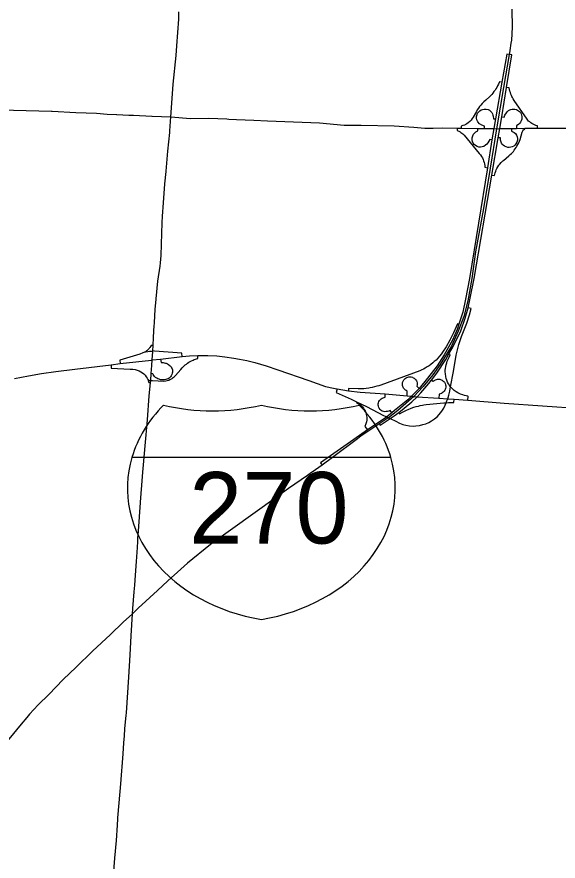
# Model space of a CAD drawing. Extents: x 0 to 34, y 0 to 22.
# Drawn here: x 7.083 to 7.784, y 16.072 to 17.165 of the extents above; entities that cross this region are included whole.
import ezdxf

# ---------------------------------------------------------------- set-up
doc = ezdxf.new("R2010")
doc.units = 0
for name, color, linetype in [('GM_X_Interchange_Ramps', 7, 'Continuous'), ('GM_X_Interstate_Route', 7, 'Continuous'), ('GM_X_Interstate_Shield', 7, 'Continuous'), ('GM_X_State_Route', 7, 'Continuous'), ('GM_X_US_Route', 7, 'Continuous')]:
    doc.layers.add(name, color=color, linetype=linetype)

msp = doc.modelspace()

# ---------------------------------------------------------------- linework, layer by layer
at = {"layer": 'GM_X_Interchange_Ramps'}
for points in [[(7.7204, 17.1167), (7.7175, 17.1172), (7.7111, 17.0809), (7.7027, 17.0331), (7.7005, 17.0206), (7.6981, 17.006), (7.6923, 16.97), (7.669, 16.8266), (7.664, 16.7998), (7.6603, 16.7829), (7.6552, 16.7672), (7.6529, 16.7605), (7.647, 16.7467), (7.6362, 16.7275), (7.627, 16.7132), (7.6148, 16.6972), (7.6039, 16.6842), (7.6023, 16.6823), (7.594, 16.674), (7.5893, 16.6692), (7.5721, 16.6553), (7.5683, 16.6523), (7.5618, 16.6472), (7.5616, 16.647), (7.537, 16.6303), (7.519, 16.6181), (7.4761, 16.5876), (7.4782, 16.5848)], [(7.5522, 16.6381), (7.5535, 16.6363), (7.5662, 16.645), (7.5715, 16.6487), (7.5774, 16.6528), (7.5845, 16.6584), (7.5943, 16.6669), (7.6011, 16.6734), (7.606, 16.6782), (7.6164, 16.6904), (7.6199, 16.6949), (7.6268, 16.7037), (7.6384, 16.7216), (7.6424, 16.7287), (7.646, 16.7352), (7.6515, 16.7451), (7.6577, 16.7587), (7.6636, 16.7752), (7.6675, 16.7885), (7.6701, 16.801), (7.6751, 16.8266), (7.698, 16.9605), (7.7063, 17.0089), (7.7083, 17.0206), (7.7083, 17.0207), (7.7108, 17.0361), (7.717, 17.0738), (7.7239, 17.1162), (7.7204, 17.1167)], [(7.7111, 17.0809), (7.7078, 17.0814), (7.7065, 17.0783), (7.7055, 17.0761), (7.7044, 17.0741), (7.7034, 17.0723), (7.7022, 17.0704), (7.7008, 17.0685), (7.6994, 17.0666), (7.6979, 17.0648), (7.697, 17.0638), (7.6956, 17.0624), (7.6902, 17.0574), (7.6877, 17.0552), (7.6856, 17.0532), (7.6837, 17.0511), (7.6822, 17.0492), (7.6807, 17.0471), (7.6792, 17.045), (7.678, 17.0429), (7.6739, 17.0356), (7.6726, 17.0336), (7.6712, 17.0317), (7.6695, 17.0299), (7.6674, 17.0282), (7.6657, 17.027), (7.6642, 17.0261), (7.6625, 17.0252), (7.6606, 17.0245), (7.6582, 17.0238), (7.6582, 17.0213)], [(7.7571, 17.0213), (7.757, 17.0242), (7.7551, 17.0248), (7.7533, 17.0255), (7.7516, 17.0263), (7.75, 17.0271), (7.7485, 17.0281), (7.7471, 17.0292), (7.7457, 17.0304), (7.7446, 17.0316), (7.7437, 17.0327), (7.7271, 17.0571), (7.7258, 17.059), (7.7247, 17.0608), (7.724, 17.0622), (7.7233, 17.0637), (7.7226, 17.0654), (7.722, 17.0672), (7.7214, 17.0692), (7.7206, 17.0733), (7.717, 17.0738)], [(7.6884, 17.0208), (7.6885, 17.0237), (7.6851, 17.025), (7.6822, 17.0267), (7.6797, 17.0294), (7.6786, 17.032), (7.6782, 17.0343), (7.6782, 17.0365), (7.6788, 17.0389), (7.6796, 17.0405), (7.681, 17.0424), (7.6824, 17.0437), (7.6842, 17.0449), (7.686, 17.0456), (7.6882, 17.046), (7.6905, 17.0459), (7.6931, 17.0452), (7.6948, 17.0444), (7.6965, 17.043), (7.6979, 17.0414), (7.6989, 17.0398), (7.6995, 17.0381), (7.6998, 17.0366), (7.7001, 17.0335), (7.7027, 17.0331)], [(7.7108, 17.0361), (7.7141, 17.0356), (7.715, 17.0379), (7.7168, 17.0412), (7.7179, 17.0425), (7.7197, 17.0441), (7.7212, 17.045), (7.7228, 17.0456), (7.7242, 17.0459), (7.7257, 17.046), (7.7278, 17.0459), (7.7299, 17.0453), (7.7313, 17.0446), (7.7326, 17.0438), (7.7339, 17.0427), (7.735, 17.0413), (7.7358, 17.0399), (7.7365, 17.0382), (7.7369, 17.0365), (7.737, 17.0349), (7.7368, 17.033), (7.7362, 17.0309), (7.7353, 17.0291), (7.734, 17.0274), (7.7329, 17.0264), (7.7298, 17.0242), (7.7299, 17.0209)], [(7.6531, 17.0214), (7.653, 17.0184), (7.6554, 17.0173), (7.6569, 17.0165), (7.658, 17.0157), (7.6593, 17.0148), (7.6606, 17.0137), (7.662, 17.0122), (7.6817, 16.9886), (7.6833, 16.9865), (7.6845, 16.9847), (7.6857, 16.9827), (7.6866, 16.9808), (7.6873, 16.9789), (7.688, 16.9769), (7.6885, 16.9749), (7.6889, 16.973), (7.6891, 16.9705), (7.6923, 16.97)], [(7.6981, 17.006), (7.6953, 17.0064), (7.6928, 17.0021), (7.6914, 17.0005), (7.6899, 16.999), (7.6878, 16.9976), (7.6856, 16.9969), (7.6833, 16.9966), (7.6811, 16.9968), (7.6788, 16.9975), (7.6769, 16.9986), (7.6752, 17.0001), (7.674, 17.0018), (7.673, 17.0039), (7.6725, 17.0061), (7.6726, 17.0089), (7.6732, 17.0112), (7.6743, 17.0133), (7.6758, 17.0151), (7.6774, 17.0164), (7.6799, 17.0177), (7.68, 17.0209)], [(7.698, 16.9605), (7.7014, 16.96), (7.7024, 16.9635), (7.703, 16.9653), (7.7037, 16.9671), (7.7046, 16.969), (7.7058, 16.9711), (7.7071, 16.9731), (7.7083, 16.9747), (7.7101, 16.9767), (7.7121, 16.9787), (7.7131, 16.9795), (7.7201, 16.9855), (7.7218, 16.9869), (7.7233, 16.9883), (7.7246, 16.9897), (7.7259, 16.991), (7.7271, 16.9925), (7.7284, 16.9943), (7.7295, 16.996), (7.7306, 16.9978), (7.7329, 17.0024), (7.7346, 17.0065), (7.7375, 17.016), (7.7381, 17.0177), (7.7391, 17.019), (7.7406, 17.02), (7.7406, 17.021)], [(7.7234, 17.0208), (7.7235, 17.0175), (7.727, 17.0157), (7.7286, 17.0141), (7.73, 17.0121), (7.7308, 17.0098), (7.7311, 17.0077), (7.7311, 17.0056), (7.7304, 17.003), (7.7293, 17.001), (7.7278, 16.9992), (7.7264, 16.9981), (7.7244, 16.997), (7.7226, 16.9964), (7.7206, 16.9962), (7.7186, 16.9963), (7.7164, 16.9969), (7.7143, 16.9979), (7.7127, 16.9992), (7.7116, 17.0004), (7.7107, 17.0019), (7.7101, 17.0032), (7.7094, 17.0056), (7.7091, 17.0085), (7.7063, 17.0089)], [(7.4975, 16.6834), (7.4965, 16.6787), (7.5156, 16.67), (7.5226, 16.6667), (7.5358, 16.6605), (7.5576, 16.6492), (7.5618, 16.6472), (7.5641, 16.6461), (7.5662, 16.645), (7.5735, 16.6415), (7.5783, 16.6391), (7.5825, 16.6375), (7.5867, 16.6364), (7.5914, 16.6356), (7.596, 16.6354), (7.5997, 16.6355), (7.6045, 16.6361), (7.6088, 16.6372), (7.6126, 16.6384), (7.6163, 16.6401), (7.62, 16.6421), (7.6236, 16.6446), (7.627, 16.6474), (7.6299, 16.6504), (7.6333, 16.6546), (7.6358, 16.6587), (7.6376, 16.6622), (7.639, 16.6656), (7.6399, 16.6678), (7.6409, 16.6706), (7.641, 16.6708), (7.6423, 16.6753), (7.6434, 16.6805), (7.6446, 16.6863), (7.6484, 16.706), (7.6519, 16.7272), (7.6535, 16.7341), (7.6551, 16.7409), (7.6587, 16.7514), (7.6654, 16.7686), (7.669, 16.7795), (7.6712, 16.7875), (7.6675, 16.7885)], [(7.6552, 16.7672), (7.6537, 16.7678), (7.6484, 16.7563), (7.6436, 16.7468), (7.6387, 16.7379), (7.6341, 16.731), (7.6326, 16.7288), (7.6303, 16.7259), (7.6281, 16.7233), (7.6258, 16.7209), (7.6235, 16.7188), (7.6215, 16.7171), (7.6188, 16.715), (7.6168, 16.7135), (7.6144, 16.712), (7.6116, 16.7103), (7.6095, 16.7092), (7.6071, 16.7081), (7.6047, 16.707), (7.5544, 16.6884), (7.5515, 16.6875), (7.549, 16.6868), (7.5458, 16.686), (7.5429, 16.6854), (7.5405, 16.685), (7.5386, 16.6846), (7.5351, 16.6841), (7.5322, 16.6837), (7.525, 16.6835), (7.5125, 16.6841), (7.5121, 16.681)], [(7.2592, 16.7397), (7.2568, 16.7398), (7.2558, 16.7382), (7.2552, 16.7373), (7.2546, 16.7366), (7.2539, 16.7357), (7.2531, 16.7349), (7.2524, 16.7342), (7.2514, 16.7333), (7.2506, 16.7326), (7.2493, 16.7317), (7.2459, 16.7301), (7.2421, 16.7286), (7.2159, 16.7206), (7.2164, 16.7163)], [(7.2587, 16.7317), (7.2572, 16.7319), (7.2562, 16.7319), (7.2545, 16.7318), (7.2523, 16.7314), (7.2498, 16.7309), (7.2493, 16.7317)], [(7.2967, 16.7256), (7.2963, 16.7297), (7.2608, 16.7324), (7.2588, 16.7326)], [(7.256, 16.6945), (7.2584, 16.6943), (7.2731, 16.6937), (7.2758, 16.694), (7.2775, 16.6944), (7.2795, 16.695), (7.2808, 16.6955), (7.2822, 16.6961), (7.2838, 16.6971), (7.2852, 16.6981), (7.2866, 16.6992), (7.2882, 16.7008), (7.2951, 16.7086), (7.2966, 16.7106), (7.2977, 16.7118), (7.2993, 16.7134), (7.3007, 16.7145), (7.3022, 16.7157), (7.3039, 16.717), (7.3054, 16.718), (7.3072, 16.719), (7.309, 16.7199), (7.3109, 16.7207), (7.3125, 16.7214), (7.317, 16.7227), (7.3171, 16.7268)], [(7.2689, 16.7222), (7.2694, 16.7178), (7.2721, 16.7175), (7.2736, 16.7172), (7.2751, 16.7169), (7.2762, 16.7166), (7.2776, 16.716), (7.279, 16.7152), (7.2801, 16.7144), (7.2814, 16.7132), (7.2824, 16.7121), (7.2831, 16.7108), (7.2837, 16.7095), (7.2841, 16.7081), (7.2842, 16.7067), (7.2842, 16.705), (7.2839, 16.7037), (7.2835, 16.7022), (7.2827, 16.7006), (7.2817, 16.6992), (7.281, 16.6983), (7.2798, 16.6973), (7.2787, 16.6967), (7.277, 16.696), (7.2755, 16.6956), (7.274, 16.6953), (7.2722, 16.6951), (7.2705, 16.6952), (7.2688, 16.6954), (7.267, 16.6959), (7.2654, 16.6965), (7.2638, 16.6973), (7.2623, 16.6984), (7.261, 16.6997), (7.2601, 16.7009), (7.2593, 16.7022), (7.2589, 16.7032), (7.2568, 16.7033)], [(7.6669, 16.669), (7.6673, 16.6738), (7.667, 16.6739), (7.6647, 16.6744), (7.6628, 16.6749), (7.6603, 16.6756), (7.6574, 16.6766), (7.654, 16.6783), (7.6516, 16.6797), (7.6492, 16.6815), (7.647, 16.6835), (7.6456, 16.685), (7.6446, 16.6863), (7.6432, 16.6881), (7.6419, 16.6901), (7.6407, 16.6924), (7.6396, 16.6949), (7.6389, 16.6971), (7.6383, 16.6995), (7.6378, 16.7028), (7.6376, 16.7054), (7.6376, 16.7077), (7.6378, 16.7099), (7.6383, 16.7127), (7.6388, 16.7148), (7.6395, 16.7171), (7.6403, 16.7192), (7.6414, 16.722), (7.6427, 16.7247), (7.6442, 16.7277), (7.6424, 16.7287)], [(7.2046, 16.7148), (7.2049, 16.7104), (7.2296, 16.7091), (7.2329, 16.7089), (7.2359, 16.7084), (7.2386, 16.7077), (7.2409, 16.7068), (7.2432, 16.7057), (7.2454, 16.7042), (7.2471, 16.7028), (7.2487, 16.7013), (7.2502, 16.6993), (7.2514, 16.6973), (7.2524, 16.6956), (7.2526, 16.695), (7.2528, 16.6938), (7.253, 16.6929), (7.2534, 16.6916), (7.2558, 16.6914)], [(7.5881, 16.6745), (7.5885, 16.6804), (7.5881, 16.6806), (7.587, 16.6812), (7.5862, 16.6818), (7.5852, 16.6826), (7.5844, 16.6835), (7.5836, 16.6845), (7.583, 16.6856), (7.5827, 16.6865), (7.5823, 16.6877), (7.5822, 16.6888), (7.5822, 16.6904), (7.5824, 16.6916), (7.5827, 16.6928), (7.5834, 16.6943), (7.5841, 16.6954), (7.5848, 16.6962), (7.5857, 16.697), (7.5868, 16.6977), (7.5879, 16.6983), (7.5892, 16.6988), (7.5903, 16.699), (7.5918, 16.6991), (7.5935, 16.6989), (7.595, 16.6985), (7.5962, 16.698), (7.5975, 16.6972), (7.5986, 16.6962), (7.5995, 16.6951), (7.6002, 16.694), (7.6007, 16.6929), (7.6011, 16.6915), (7.6013, 16.6901), (7.6012, 16.6888), (7.601, 16.6872), (7.6039, 16.6842)], [(7.2524, 16.6956), (7.2528, 16.6957), (7.2536, 16.6949), (7.2545, 16.6944), (7.256, 16.6945)], [(7.6199, 16.6949), (7.6219, 16.6935), (7.6232, 16.6944), (7.6249, 16.6953), (7.6262, 16.6958), (7.6276, 16.696), (7.629, 16.6961), (7.6305, 16.6959), (7.6323, 16.6953), (7.6335, 16.6948), (7.6347, 16.6939), (7.6358, 16.6929), (7.6365, 16.692), (7.6374, 16.6905), (7.6379, 16.6889), (7.6382, 16.6873), (7.6382, 16.6859), (7.638, 16.6842), (7.6376, 16.6829), (7.6371, 16.6818), (7.6361, 16.6804), (7.6351, 16.6793), (7.6338, 16.6783), (7.6326, 16.6777), (7.6296, 16.6766), (7.6292, 16.6714)], [(7.5226, 16.6667), (7.5222, 16.666), (7.5241, 16.6651), (7.5262, 16.6638), (7.5283, 16.6622), (7.5303, 16.6602), (7.5317, 16.6584), (7.5328, 16.6567), (7.5337, 16.6551), (7.5346, 16.653), (7.5353, 16.6508), (7.5357, 16.6487), (7.5359, 16.6467), (7.536, 16.6451), (7.5359, 16.6429), (7.5356, 16.6409), (7.5349, 16.6384), (7.5336, 16.6348), (7.537, 16.6303)], [(7.5683, 16.6523), (7.5661, 16.6553), (7.5646, 16.6548), (7.5628, 16.6543), (7.5611, 16.654), (7.5594, 16.6539), (7.5575, 16.6542), (7.5559, 16.6548), (7.5546, 16.6557), (7.5532, 16.6569), (7.5522, 16.6583), (7.5516, 16.6594), (7.551, 16.6612), (7.5508, 16.6626), (7.5509, 16.6643), (7.5512, 16.6656), (7.5518, 16.6671), (7.5525, 16.6683), (7.5535, 16.6695), (7.5548, 16.6706), (7.5561, 16.6714), (7.5596, 16.6727), (7.5598, 16.6769)], [(7.5774, 16.6528), (7.5785, 16.6513), (7.5824, 16.6534), (7.5847, 16.6546), (7.5875, 16.6559), (7.5898, 16.6569), (7.5935, 16.6583), (7.5971, 16.6596), (7.6, 16.6605), (7.6028, 16.6613), (7.6053, 16.6619), (7.608, 16.6625), (7.6099, 16.6628), (7.613, 16.6633), (7.6359, 16.6655), (7.639, 16.6656), (7.642, 16.6658), (7.6485, 16.6659), (7.6489, 16.6659), (7.6492, 16.6701)]]:
    msp.add_lwpolyline(points, dxfattribs=at)
at = {"layer": 'GM_X_Interstate_Route'}
for points in [[(7.7035, 17.2643), (7.7043, 17.2625), (7.7105, 17.2452), (7.715, 17.2301), (7.7173, 17.2204), (7.7195, 17.2114), (7.7209, 17.2028), (7.7225, 17.1903), (7.724, 17.1751), (7.7244, 17.1521), (7.7233, 17.1351), (7.7227, 17.1314)], [(7.7227, 17.1314), (7.7213, 17.1219), (7.7213, 17.1216)], [(7.7204, 17.1167), (7.7132, 17.0737), (7.7086, 17.0482), (7.704, 17.0205)], [(7.7213, 17.1216), (7.7204, 17.1167)], [(7.704, 17.0205), (7.6957, 16.9693), (7.6872, 16.9172), (7.6767, 16.861), (7.6722, 16.8266), (7.667, 16.7974), (7.6618, 16.7773), (7.6545, 16.7583), (7.6457, 16.739), (7.631, 16.715), (7.6217, 16.7018), (7.6092, 16.6867), (7.5971, 16.6737)], [(7.0796, 16.6969), (7.0975, 16.7006), (7.1146, 16.7035), (7.1331, 16.7062), (7.1577, 16.7092), (7.2046, 16.7148), (7.2164, 16.7163), (7.257, 16.7208)], [(7.257, 16.7208), (7.2581, 16.721), (7.2689, 16.7222), (7.2967, 16.7256), (7.3061, 16.7264), (7.3171, 16.7268), (7.3301, 16.7267), (7.3417, 16.7261), (7.3522, 16.7249), (7.3637, 16.7234), (7.3709, 16.7222), (7.3805, 16.7203), (7.391, 16.7178), (7.4055, 16.7135), (7.4208, 16.708), (7.4609, 16.6943), (7.4825, 16.6867), (7.4927, 16.6844), (7.495, 16.6839)], [(7.495, 16.6839), (7.4975, 16.6834), (7.5121, 16.681), (7.5272, 16.6792), (7.5598, 16.6769)], [(7.5971, 16.6737), (7.5901, 16.6677), (7.5761, 16.6555), (7.5641, 16.6461), (7.5639, 16.6459), (7.5522, 16.6381)], [(7.5598, 16.6769), (7.5881, 16.6745), (7.594, 16.674), (7.5971, 16.6737)], [(7.5971, 16.6737), (7.6011, 16.6734), (7.6292, 16.6714), (7.6409, 16.6706), (7.6411, 16.6706), (7.6492, 16.6701)], [(7.6492, 16.6701), (7.6492, 16.6701), (7.6669, 16.669)], [(7.6669, 16.669), (7.7139, 16.665), (7.8134, 16.658), (7.8474, 16.6549), (7.8496, 16.6547), (7.8795, 16.6518), (7.8914, 16.651)], [(7.5522, 16.6381), (7.5522, 16.6381), (7.5282, 16.6221), (7.5239, 16.6189)], [(7.5239, 16.6189), (7.4914, 16.5946), (7.4782, 16.5848)], [(7.4695, 16.5787), (7.4627, 16.574), (7.4591, 16.5714)], [(7.4782, 16.5848), (7.4695, 16.5787)], [(7.4591, 16.5714), (7.4347, 16.5544), (7.4171, 16.5421), (7.3335, 16.482), (7.3038, 16.4579), (7.2951, 16.4501), (7.2782, 16.4349), (7.2648, 16.4223), (7.2397, 16.3993), (7.2323, 16.392)], [(7.2323, 16.392), (7.2205, 16.3813), (7.2038, 16.3654)], [(7.2038, 16.3654), (7.1807, 16.3437), (7.1593, 16.3231), (7.1425, 16.3072), (7.1238, 16.2875), (7.1103, 16.2742), (7.0991, 16.2622), (7.0954, 16.2578)], [(7.0954, 16.2578), (7.0883, 16.2494), (7.0724, 16.2299), (7.0618, 16.2174)]]:
    msp.add_lwpolyline(points, dxfattribs=at)
at = {"layer": 'GM_X_Interstate_Shield'}
msp.add_line((7.5672, 16.5945), (7.2316, 16.5945), dxfattribs=at)
msp.add_line((7.5672, 16.5945), (7.2316, 16.5945), dxfattribs=at)
for centre, start_param, end_param in [((7.4428, 16.5549), 2.47259, 2.911027), ((7.336, 16.8285), 4.415841, 5.008937), ((7.4628, 16.8285), 4.415841, 5.008937), ((7.356, 16.5549), 0.230566, 0.669003), ((7.4428, 16.5549), 2.911027, 4.511031), ((7.356, 16.5549), 4.913747, 6.513751)]:
    msp.add_ellipse(centre, major_axis=(0.2169, 0), ratio=0.8, start_param=start_param, end_param=end_param, dxfattribs=at)
at = {"layer": 'GM_X_State_Route'}
for points in [[(7.2899, 17.128), (7.2924, 17.1622), (7.2924, 17.1709), (7.2925, 17.1717)], [(7.2823, 17.0358), (7.2853, 17.0776), (7.2853, 17.078), (7.289, 17.1153), (7.2899, 17.128)], [(7.2759, 16.9656), (7.2764, 16.9706), (7.2782, 16.9915), (7.2807, 17.0156), (7.2809, 17.0179), (7.2823, 17.0358)], [(7.27, 16.8708), (7.2708, 16.8987), (7.2714, 16.9071), (7.2727, 16.9246), (7.2745, 16.9492), (7.2759, 16.965), (7.2759, 16.9653), (7.2759, 16.9656)], [(7.2687, 16.8467), (7.2696, 16.8562), (7.27, 16.8708)], [(7.2607, 16.7659), (7.2608, 16.7677), (7.2609, 16.7695), (7.262, 16.7863), (7.2629, 16.7997), (7.2629, 16.8), (7.2651, 16.8231), (7.2683, 16.8423), (7.2687, 16.8467)], [(7.2584, 16.7266), (7.2587, 16.7317), (7.2588, 16.7326), (7.2592, 16.7397), (7.2598, 16.7499), (7.2607, 16.7659)], [(7.2576, 16.7136), (7.2581, 16.721), (7.2584, 16.7266)], [(7.2487, 16.6096), (7.252, 16.6434), (7.2542, 16.6746), (7.2542, 16.6746), (7.2558, 16.6914), (7.256, 16.6945), (7.2568, 16.7033), (7.2576, 16.7136)], [(7.2395, 16.4901), (7.2402, 16.4991), (7.2427, 16.5364), (7.2427, 16.5367), (7.2454, 16.5702), (7.2454, 16.5705), (7.2487, 16.6096)], [(7.2387, 16.4781), (7.2393, 16.4857), (7.2395, 16.49), (7.2395, 16.4901)], [(7.2362, 16.4422), (7.2362, 16.4422), (7.2375, 16.4601), (7.2387, 16.478), (7.2387, 16.4781)], [(7.2346, 16.4207), (7.2346, 16.4207), (7.2353, 16.4291), (7.2362, 16.4422)], [(7.2329, 16.3992), (7.2329, 16.3992), (7.2346, 16.4207)], [(7.2309, 16.3635), (7.2323, 16.392), (7.2329, 16.3992)], [(7.2294, 16.3392), (7.2309, 16.3635)], [(7.2275, 16.31), (7.2294, 16.3392)], [(7.2245, 16.2639), (7.2275, 16.31)], [(7.214, 16.1328), (7.2173, 16.1721), (7.2204, 16.2108), (7.2213, 16.2249), (7.2221, 16.2342), (7.2227, 16.2433), (7.2235, 16.2521), (7.2242, 16.2605), (7.2245, 16.2639)], [(7.2136, 16.1279), (7.214, 16.1328)], [(7.2129, 16.1182), (7.2135, 16.1266), (7.2136, 16.1279)], [(7.2009, 15.9663), (7.2026, 15.9848), (7.2096, 16.0757), (7.2115, 16.0987), (7.2129, 16.1182)]]:
    msp.add_lwpolyline(points, dxfattribs=at)
at = {"layer": 'GM_X_US_Route'}
for points in [[(6.9246, 17.0518), (6.9336, 17.0514), (6.9641, 17.05), (6.9731, 17.0494), (6.9741, 17.0494), (7.0205, 17.0472), (7.0569, 17.0455), (7.0572, 17.0455), (7.0783, 17.0447), (7.1275, 17.0431), (7.1283, 17.0431), (7.1589, 17.0416), (7.1726, 17.0411), (7.1858, 17.0405), (7.1995, 17.0395), (7.2116, 17.0389), (7.2121, 17.0389), (7.2276, 17.0382), (7.2338, 17.0379), (7.2573, 17.0368), (7.258, 17.0368), (7.2823, 17.0358)], [(7.2823, 17.0358), (7.3075, 17.0336), (7.3314, 17.0342), (7.3546, 17.0331), (7.3573, 17.033)], [(7.3573, 17.033), (7.3673, 17.0326)], [(7.3673, 17.0326), (7.3898, 17.0317)], [(7.3898, 17.0317), (7.4073, 17.0309), (7.4746, 17.0281), (7.5068, 17.0253), (7.5289, 17.0249), (7.5713, 17.0243), (7.5971, 17.0223)], [(7.5971, 17.0223), (7.6113, 17.0213), (7.6218, 17.0214)], [(7.6218, 17.0214), (7.6342, 17.0216), (7.6531, 17.0214), (7.6582, 17.0213), (7.68, 17.0209), (7.6884, 17.0208), (7.7005, 17.0206), (7.704, 17.0205)], [(7.704, 17.0205), (7.7083, 17.0206), (7.7234, 17.0208), (7.7299, 17.0209), (7.7406, 17.021), (7.7571, 17.0213), (7.7743, 17.0214)], [(7.7743, 17.0214), (7.7808, 17.0214), (7.7944, 17.0212), (7.7957, 17.0213)]]:
    msp.add_lwpolyline(points, dxfattribs=at)

# ---------------------------------------------------------------- texts
at = {"layer": 'GM_X_Interstate_Shield'}
msp.add_text('270', height=0.09255, dxfattribs=at).set_placement((7.3059, 16.4832))

doc.saveas('drawing.dxf')
